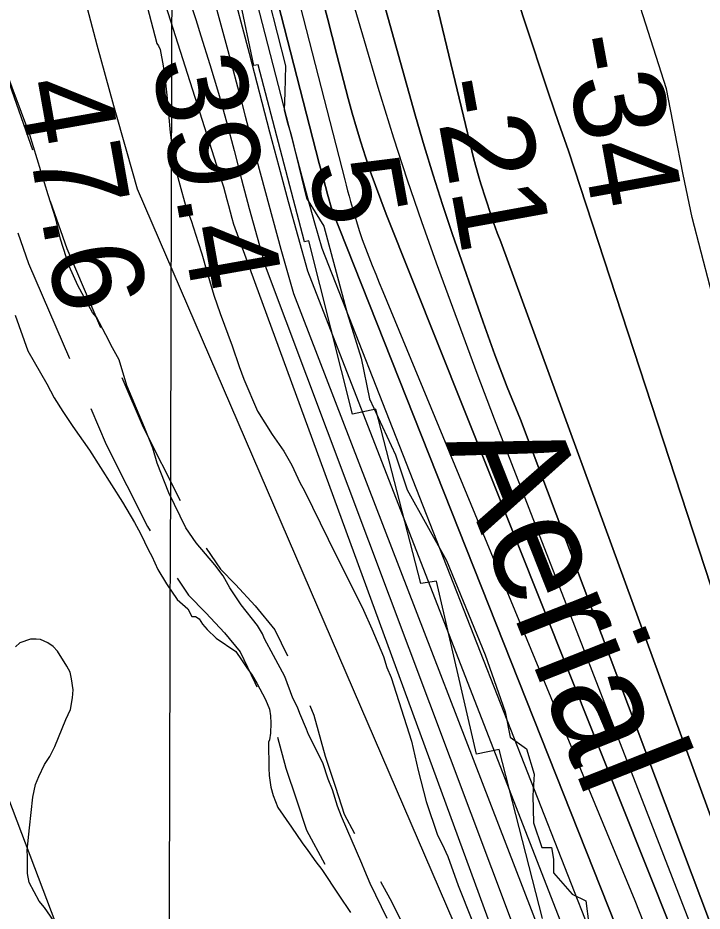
# Model space of a CAD drawing. Extents: x 3161665 to 3199565, y 885729 to 911164.
# Drawn here: x 3176224 to 3176727, y 893695 to 894352 of the extents above; entities that cross this region are included whole.
import ezdxf

# ---------------------------------------------------------------- set-up
doc = ezdxf.new("R2010")
doc.units = 0
for name, color, linetype in [('V-GRID-MAJR', 7, 'Continuous'), ('V-RIVR-EDGE', 7, 'Continuous'), ('V-RIVR-IDEN', 7, 'Continuous'), ('V-RIVR-RANG', 7, 'Continuous'), ('V-ROAD-CNTR', 7, 'Continuous'), ('V-RRAP-RVMT', 7, 'Continuous'), ('V-SITE-VEGE', 7, 'Continuous'), ('V-TOPO-DPTH', 7, 'Continuous'), ('V-TOPO-MAJR', 7, 'Continuous'), ('V-TOPO-MINR', 7, 'Continuous'), ('V-TOPO-WATR', 7, 'Continuous')]:
    doc.layers.add(name, color=color, linetype=linetype)

msp = doc.modelspace()

# ---------------------------------------------------------------- linework, layer by layer
at = {"layer": 'V-GRID-MAJR'}
msp.add_spline([(3176327.96, 891166.6), (3176345.58, 897226.3), (3176363.22, 903289.08), (3176380.86, 909351.9), (3176380.87, 909354.94)], degree=3, dxfattribs=at)
at = {"layer": 'V-RIVR-EDGE'}
for points in [[(3176294.76, 894759.71), (3176301.86, 894737.76), (3176313.25, 894714.84), (3176322.26, 894694.79), (3176326.51, 894678.57), (3176326.49, 894668.07), (3176330.26, 894651.37), (3176340.18, 894610.82), (3176343.47, 894594.12), (3176349.58, 894555.47), (3176354.81, 894552.12), (3176358.57, 894529.7), (3176365.2, 894509.66), (3176375.62, 894479.59), (3176392.64, 894422.8), (3176408.24, 894365.06), (3176420.52, 894316.86)], [(3176420.52, 894316.86), (3176419.99, 894297.31), (3176419.48, 894284.44), (3176421.85, 894275.85), (3176424.68, 894266.3), (3176436.01, 894219.54), (3176448.84, 894199), (3176465.85, 894135.06), (3176476.26, 894102.13), (3176482.38, 894072.07), (3176501.36, 894031.01), (3176509.88, 894005.24), (3176538.84, 893953.19), (3176567.28, 893883.97), (3176581.96, 893841.97), (3176585.73, 893823.36), (3176597.63, 893814.75), (3176603.3, 893796.14), (3176602.31, 893780.4), (3176602.74, 893760.37), (3176608.89, 893742.24), (3176616.05, 893742.22), (3176617.46, 893733.63), (3176617.43, 893723.62), (3176631.22, 893707.85), (3176641.22, 893703.05), (3176643.57, 893685.88)]]:
    msp.add_lwpolyline(points, dxfattribs=at)
at = {"layer": 'V-ROAD-CNTR'}
for points in [[(3176198.7, 894348.48), (3176199.62, 894345.85), (3176208.86, 894325.5), (3176216.14, 894308.46), (3176234.6, 894255.23)], [(3176247.7, 894217.44), (3176259.8, 894182.54), (3176284.62, 894124.57)], [(3176223.98, 894194.27), (3176231.81, 894171.71), (3176261.76, 894101.73)], [(3176300.36, 894087.79), (3176315.98, 894051.3), (3176343.09, 893997.44)], [(3176277.5, 894064.96), (3176288.76, 894038.64), (3176319.15, 893978.28), (3176320.99, 893974.96)], [(3176362.27, 893962.34), (3176362.32, 893962.24), (3176372.75, 893946.78), (3176383.73, 893935.48), (3176398.35, 893919.8), (3176412.62, 893902.36), (3176422.04, 893883.02)], [(3176340.93, 893940.31), (3176349.38, 893927.78), (3176362, 893914.8), (3176375.74, 893900.06), (3176387.18, 893886.08), (3176398.13, 893863.6), (3176399.56, 893860.34)], [(3176438.34, 893846.49), (3176441.42, 893839.42), (3176449.61, 893809.32), (3176457.25, 893786.5), (3176463.59, 893766.81), (3176471.38, 893752.45)], [(3176414.7, 893823.37), (3176420.89, 893800.61), (3176428.74, 893777.13), (3176435.89, 893754.95), (3176449.41, 893730.04)], [(3176490.46, 893717.29), (3176497.28, 893704.73), (3176536, 893628.32)]]:
    msp.add_lwpolyline(points, dxfattribs=at)
at = {"layer": 'V-RRAP-RVMT'}
for p, q in [((3176397.39, 894317.14), (3176370.51, 894442.62)), ((3176400.51, 894317.72), (3176397.39, 894317.14)), ((3176434.47, 894187.53), (3176400.51, 894317.72)), ((3176437.79, 894188.4), (3176434.47, 894187.53)), ((3176469.75, 894060.76), (3176437.79, 894188.4)), ((3176486.88, 894064.41), (3176469.75, 894060.76)), ((3176520.03, 893936.3), (3176486.88, 894064.41)), ((3176531.53, 893938), (3176520.03, 893936.3)), ((3176560.82, 893810.8), (3176531.53, 893938)), ((3176577.55, 893814.21), (3176560.82, 893810.8)), ((3176609.54, 893690.09), (3176577.55, 893814.21))]:
    msp.add_line(p, q, dxfattribs=at)
at = {"layer": 'V-SITE-VEGE'}
for p, q in [((3176221.9, 894133.61), (3176231.13, 894107.36)), ((3176231.13, 894107.36), (3176245.24, 894083.12)), ((3176245.24, 894083.12), (3176250.63, 894072.96)), ((3176250.63, 894072.96), (3176256.93, 894062.84)), ((3176256.93, 894062.84), (3176264.16, 894051.86)), ((3176264.16, 894051.86), (3176276.64, 894034.33)), ((3176276.64, 894034.33), (3176300.82, 893996.07)), ((3176300.82, 893996.07), (3176309.57, 893981.09)), ((3176309.57, 893981.09), (3176313.97, 893973.15)), ((3176313.97, 893973.15), (3176319.91, 893960.76)), ((3176319.91, 893960.76), (3176322.35, 893956.34)), ((3176322.35, 893956.34), (3176326.82, 893946.6)), ((3176326.82, 893946.6), (3176333.13, 893936.03)), ((3176333.13, 893936.03), (3176340.84, 893924.62)), ((3176340.84, 893924.62), (3176348.8, 893917.73)), ((3176348.8, 893917.73), (3176351.75, 893911.98)), ((3176351.75, 893911.98), (3176354.45, 893912.1)), ((3176354.45, 893912.1), (3176357.23, 893910.41)), ((3176357.23, 893910.41), (3176359.66, 893906.45)), ((3176359.66, 893906.45), (3176362.98, 893902.52)), ((3176362.98, 893902.52), (3176369.58, 893896.03)), ((3176233.27, 893895.27), (3176225.25, 893892.67)), ((3176237.33, 893895.44), (3176233.27, 893895.27)), ((3176240.5, 893895.12), (3176237.33, 893895.44)), ((3176246.02, 893892.64), (3176240.5, 893895.12)), ((3176369.58, 893896.03), (3176383.98, 893886.25)), ((3176225.25, 893892.67), (3176222.21, 893889.84)), ((3176249.74, 893890.09), (3176246.02, 893892.64)), ((3176253.05, 893886.62), (3176249.74, 893890.09)), ((3176259.83, 893875.62), (3176253.05, 893886.62)), ((3176383.98, 893886.25), (3176388.3, 893880.11)), ((3176262.27, 893871.21), (3176259.83, 893875.62)), ((3176388.3, 893880.11), (3176392.64, 893873.52)), ((3176263.38, 893866.29), (3176262.27, 893871.21)), ((3176392.64, 893873.52), (3176395.52, 893869.58)), ((3176395.52, 893869.58), (3176399.41, 893862.97)), ((3176264.62, 893858.21), (3176263.38, 893866.29)), ((3176399.41, 893862.97), (3176405.78, 893851.05)), ((3176263.97, 893852.32), (3176264.62, 893858.21)), ((3176262.53, 893843.68), (3176263.97, 893852.32)), ((3176405.78, 893851.05), (3176408.78, 893843.95)), ((3176259.22, 893836.32), (3176262.53, 893843.68)), ((3176408.78, 893843.95), (3176409.44, 893839.01)), ((3176251.02, 893816.56), (3176259.22, 893836.32)), ((3176409.44, 893839.01), (3176409.67, 893833.61)), ((3176409.67, 893833.61), (3176409.52, 893826.38)), ((3176409.52, 893826.38), (3176408.83, 893821.38)), ((3176247.27, 893809.18), (3176251.02, 893816.56)), ((3176408.83, 893821.38), (3176408, 893819.54)), ((3176408, 893819.54), (3176408.35, 893800.6)), ((3176243.46, 893803.15), (3176247.27, 893809.18)), ((3176239.32, 893794.4), (3176243.46, 893803.15)), ((3176408.35, 893800.6), (3176408.58, 893795.19)), ((3176236.86, 893788.43), (3176239.32, 893794.4)), ((3176408.58, 893795.19), (3176409.83, 893786.66)), ((3176234.98, 893779.32), (3176236.86, 893788.43)), ((3176409.83, 893786.66), (3176411.45, 893780.41)), ((3176232.32, 893756.63), (3176234.98, 893779.32)), ((3176411.45, 893780.41), (3176414.99, 893771.53)), ((3176414.99, 893771.53), (3176425.07, 893757.06)), ((3176230.75, 893740.32), (3176232.32, 893756.63)), ((3176425.07, 893757.06), (3176432.78, 893745.64)), ((3176432.78, 893745.64), (3176437.08, 893739.96)), ((3176230.96, 893735.36), (3176230.75, 893740.32)), ((3176437.08, 893739.96), (3176442.85, 893731.62)), ((3176231.02, 893723.17), (3176230.96, 893735.36)), ((3176442.85, 893731.62), (3176447.15, 893725.93)), ((3176232.21, 893716.45), (3176231.02, 893723.17)), ((3176447.15, 893725.93), (3176459.68, 893707.05)), ((3176239.55, 893702.77), (3176232.21, 893716.45)), ((3176459.68, 893707.05), (3176468.34, 893694.32)), ((3176243.37, 893697.96), (3176239.55, 893702.77)), ((3176254.9, 893681.29), (3176243.37, 893697.96))]:
    msp.add_line(p, q, dxfattribs=at)
for points in [[(3176318.9, 894360.69), (3176325.91, 894333.45), (3176327.34, 894331.71), (3176328.36, 894329.04), (3176330.67, 894316.95), (3176331.91, 894308.87), (3176333.38, 894295.39), (3176335.89, 894267.96), (3176338.68, 894244.6), (3176347.17, 894214.26), (3176351.25, 894203.15), (3176356.44, 894187.11), (3176359.05, 894178.64), (3176362.76, 894165.71), (3176368, 894148.32), (3176372.63, 894134.97), (3176381.31, 894110.96), (3176386.46, 894095.83), (3176390.01, 894086.5), (3176400.03, 894062.99), (3176410.68, 894045.83), (3176419.33, 894033.55), (3176425.17, 894023.41), (3176431.13, 894010.57), (3176434.55, 894004.4), (3176451.83, 893969.01), (3176477.95, 893916.83), (3176483.95, 893903.09), (3176492.48, 893882.68), (3176495.07, 893874.67), (3176498.1, 893867.12), (3176513.16, 893820.35), (3176518.12, 893798.89), (3176524.04, 893776.11), (3176532.31, 893751.18), (3176535.75, 893744.55), (3176539.74, 893735.69), (3176547.41, 893714.34)], [(3176495.16, 893690.03), (3176482.79, 893715.69), (3176478.79, 893725), (3176476.76, 893730.34), (3176461.76, 893764.92), (3176458.74, 893772.47), (3176455.07, 893784.5), (3176452.03, 893792.5), (3176447.91, 893804.52), (3176437.56, 893825.3), (3176436.03, 893829.3), (3176431.04, 893840.83), (3176429.49, 893845.28), (3176426.06, 893851.9), (3176419.97, 893867.9), (3176411.64, 893883.35), (3176405.25, 893895.72), (3176403.75, 893899.27), (3176399.88, 893905.43), (3176387.95, 893920.73), (3176379.76, 893933.02), (3176374.87, 893941.85), (3176368.66, 893950.16), (3176354.89, 893966.29), (3176347.2, 893977.25), (3176334.84, 894002.92), (3176326.25, 894024.68), (3176323.07, 894035.83), (3176317.02, 894050.92), (3176303.98, 894081.98), (3176298.23, 894100.7), (3176293.34, 894109.52), (3176288.42, 894119.24), (3176281.56, 894132.05), (3176278.7, 894135.54), (3176267.94, 894155.4), (3176261.47, 894169.58), (3176255.21, 894189.63), (3176251.88, 894204.39), (3176246.17, 894222.2), (3176232.58, 894266.33), (3176207.16, 894333.88)], [(3176547.41, 893714.34), (3176557.5, 893689.04)]]:
    msp.add_lwpolyline(points, dxfattribs=at)
at = {"layer": 'V-TOPO-DPTH'}
for points in [[(3176701.72, 893587.62), (3176454.57, 894211.21), (3176451.43, 894222.51), (3176448.39, 894233.82), (3176445.42, 894245.16), (3176396.2, 894436.23), (3176377.64, 894508.46), (3176359.12, 894580.69), (3176340.69, 894652.95), (3176322.3, 894725.22), (3176300.56, 894810.9)], [(3176701.72, 893587.62), (3176454.57, 894211.21), (3176451.43, 894222.51), (3176448.39, 894233.82), (3176445.42, 894245.16), (3176396.2, 894436.23), (3176377.64, 894508.46), (3176359.12, 894580.69), (3176340.69, 894652.95), (3176322.3, 894725.22), (3176300.56, 894810.9)], [(3176474.19, 894812.27), (3176539.01, 894548.12), (3176551.8, 894498.57), (3176565.37, 894449.24), (3176580.12, 894400.26), (3176595.65, 894351.5), (3176614.05, 894296.04), (3176621.17, 894275.25), (3176628.57, 894254.57), (3176855.03, 893561.59), (3176864.47, 893534.44), (3176874.25, 893507.41), (3176905.05, 893424.69), (3176928.25, 893364.03), (3176952.17, 893303.67), (3176977.16, 893243.75), (3177002.88, 893184.12), (3177037.17, 893106.53), (3177046.52, 893086.03), (3177056.18, 893065.69), (3177066.33, 893045.59), (3177076.79, 893025.64), (3177087.65, 893005.9)], [(3177087.65, 893005.9), (3177076.79, 893025.64), (3177066.33, 893045.59), (3177056.18, 893065.69), (3177046.52, 893086.03), (3177037.17, 893106.53), (3177002.88, 893184.12), (3176977.16, 893243.75), (3176952.17, 893303.67), (3176928.25, 893364.03), (3176905.05, 893424.69), (3176874.25, 893507.41), (3176864.47, 893534.44), (3176855.03, 893561.59), (3176628.57, 894254.57), (3176621.17, 894275.25), (3176614.05, 894296.04), (3176595.65, 894351.5), (3176580.12, 894400.26), (3176565.37, 894449.24), (3176551.8, 894498.57), (3176539.01, 894548.12), (3176474.19, 894812.27)], [(3176378.37, 894796.48), (3176432.92, 894586.18), (3176448.26, 894527.72), (3176463.81, 894469.33), (3176479.69, 894411.02), (3176495.78, 894352.77), (3176516.14, 894279.85), (3176522.42, 894258.17), (3176528.96, 894236.56), (3176535.91, 894215.08), (3176543.12, 894193.69), (3176565.75, 894128.57), (3176574.44, 894104.53), (3176583.53, 894080.64), (3176593.22, 894056.99), (3176785.41, 893546.84)], [(3176785.41, 893546.84), (3176593.22, 894056.99), (3176583.53, 894080.64), (3176574.44, 894104.53), (3176565.75, 894128.57), (3176543.12, 894193.69), (3176535.91, 894215.08), (3176528.96, 894236.56), (3176522.42, 894258.17), (3176516.14, 894279.85), (3176495.78, 894352.77), (3176479.69, 894411.02), (3176463.81, 894469.33), (3176448.26, 894527.72), (3176432.92, 894586.18), (3176378.37, 894796.48)], [(3176429.03, 894790.23), (3176441.16, 894739.42), (3176453.3, 894688.61), (3176465.46, 894637.81), (3176477.63, 894587.02), (3176557.4, 894254.39), (3176558.94, 894248.28), (3176560.57, 894242.2), (3176562.33, 894236.15), (3176564.18, 894230.13), (3176571.35, 894207.76), (3176573.68, 894200.96), (3176576.17, 894194.23), (3176578.93, 894187.59), (3176812.57, 893547.36)], [(3176812.57, 893547.36), (3176578.93, 894187.59), (3176576.17, 894194.23), (3176573.68, 894200.96), (3176571.35, 894207.76), (3176564.18, 894230.13), (3176562.33, 894236.15), (3176560.57, 894242.2), (3176558.94, 894248.28), (3176557.4, 894254.39), (3176477.63, 894587.02), (3176465.46, 894637.81), (3176453.3, 894688.61), (3176441.16, 894739.42), (3176429.03, 894790.23)], [(3176266.9, 894771.62), (3176333.82, 894543.75), (3176349.45, 894489.57), (3176364.72, 894435.3), (3176379.47, 894380.89), (3176393.87, 894326.38), (3176408.84, 894268.55), (3176415.58, 894242.9), (3176422.46, 894217.29), (3176429.52, 894191.74), (3176436.72, 894166.21), (3176659.83, 893591.97)], [(3176723.83, 893632.92), (3176494.51, 894207.93), (3176490.51, 894218.39), (3176486.62, 894228.89), (3176482.9, 894239.45), (3176479.31, 894250.06), (3176475.9, 894260.73), (3176472.63, 894271.44), (3176469.57, 894282.21), (3176466.65, 894293.02), (3176458.31, 894325.08), (3176451.32, 894351.95), (3176444.33, 894378.83), (3176437.34, 894405.7), (3176430.36, 894432.58), (3176370.31, 894663.81), (3176361.21, 894699.06), (3176352.17, 894734.32), (3176343.24, 894769.61)], [(3176343.24, 894769.61), (3176352.17, 894734.32), (3176361.21, 894699.06), (3176370.31, 894663.81), (3176430.36, 894432.58), (3176437.34, 894405.7), (3176444.33, 894378.83), (3176451.32, 894351.95), (3176458.31, 894325.08), (3176466.65, 894293.02), (3176469.57, 894282.21), (3176472.63, 894271.44), (3176475.9, 894260.73), (3176479.31, 894250.06), (3176482.9, 894239.45), (3176486.62, 894228.89), (3176490.51, 894218.39), (3176494.51, 894207.93), (3176723.83, 893632.92)]]:
    msp.add_lwpolyline(points, dxfattribs=at)
at = {"layer": 'V-TOPO-MAJR'}
for points in [[(3176197.14, 894785.58), (3176371.51, 894238.53), (3176372.03, 894236.97), (3176373.49, 894232.46), (3176374.88, 894227.92), (3176376.17, 894223.35), (3176377.39, 894218.76), (3176378.58, 894214.17), (3176379.8, 894209.58), (3176381.04, 894204.99), (3176382.31, 894200.42), (3176605.45, 893591.02)], [(3177266.38, 892869.65), (3176888.97, 893555.49), (3176884.77, 893568.13), (3176719.38, 894205.41), (3176712.92, 894236.95), (3176706.65, 894268.53), (3176700.65, 894300.16), (3176561.53, 894735.82), (3176550.46, 894770.02)]]:
    msp.add_lwpolyline(points, dxfattribs=at)
at = {"layer": 'V-TOPO-MINR'}
for points in [[(3176212.29, 894808.98), (3176230.66, 894733.5), (3176345.79, 894377.75), (3176354.6, 894350.93), (3176358.44, 894338.97), (3176364.98, 894318.01), (3176371.26, 894296.98), (3176377.16, 894275.84), (3176382.8, 894254.62), (3176388.34, 894233.37), (3176393.98, 894212.15), (3176399.77, 894190.97), (3176405.67, 894169.82), (3176602.22, 893646.03)], [(3177087.65, 893005.9), (3177076.79, 893025.64), (3177066.33, 893045.59), (3177056.18, 893065.69), (3177046.52, 893086.03), (3177037.17, 893106.53), (3177002.88, 893184.12), (3176977.16, 893243.75), (3176952.17, 893303.67), (3176928.25, 893364.03), (3176905.05, 893424.69), (3176874.25, 893507.41), (3176864.47, 893534.44), (3176855.03, 893561.59), (3176628.57, 894254.57), (3176621.17, 894275.25), (3176614.05, 894296.04), (3176595.65, 894351.5), (3176580.12, 894400.26), (3176565.37, 894449.24), (3176551.8, 894498.57), (3176539.01, 894548.12), (3176474.19, 894812.27)], [(3176378.37, 894796.48), (3176432.92, 894586.18), (3176448.26, 894527.72), (3176463.81, 894469.33), (3176479.69, 894411.02), (3176495.78, 894352.77), (3176516.14, 894279.85), (3176522.42, 894258.17), (3176528.96, 894236.56), (3176535.91, 894215.08), (3176543.12, 894193.69), (3176565.75, 894128.57), (3176574.44, 894104.53), (3176583.53, 894080.64), (3176593.22, 894056.99), (3176785.41, 893546.84)], [(3176237.21, 894792.25), (3176245.63, 894759.57), (3176254.61, 894727.06), (3176264.46, 894694.8), (3176274.88, 894662.7), (3176277.82, 894654.02), (3176289.99, 894617.66), (3176301.95, 894581.23), (3176313.6, 894544.7), (3176325.05, 894508.11), (3176345.67, 894441.23), (3176356.94, 894403.72), (3176367.86, 894366.12), (3176378.26, 894328.36), (3176388.29, 894290.5), (3176390.99, 894280.05), (3176399.54, 894247.37), (3176408.25, 894214.74), (3176417.21, 894182.17), (3176426.33, 894149.65), (3176649.02, 893572.21)], [(3176289.07, 894792.73), (3176325.52, 894650.59), (3176343.96, 894578.78), (3176362.42, 894506.97), (3176380.94, 894435.17), (3176399.48, 894363.38), (3176427.01, 894256.93), (3176431.88, 894238.39), (3176436.85, 894219.88), (3176441.98, 894201.42), (3176447.2, 894182.97), (3176692.44, 893557.31)], [(3176812.57, 893547.36), (3176578.93, 894187.59), (3176576.17, 894194.23), (3176573.68, 894200.96), (3176571.35, 894207.76), (3176564.18, 894230.13), (3176562.33, 894236.15), (3176560.57, 894242.2), (3176558.94, 894248.28), (3176557.4, 894254.39), (3176477.63, 894587.02), (3176465.46, 894637.81), (3176453.3, 894688.61), (3176441.16, 894739.42), (3176429.03, 894790.23)], [(3176356.95, 894781.94), (3176367.71, 894741.69), (3176377.38, 894705.54), (3176387.07, 894669.38), (3176396.79, 894633.24), (3176406.52, 894597.1), (3176449.18, 894438.88), (3176458.64, 894404.4), (3176468.3, 894369.97), (3176478.27, 894335.64), (3176488.43, 894301.36), (3176490.4, 894294.83), (3176500.01, 894263.95), (3176509.97, 894233.19), (3176520.48, 894202.61), (3176531.35, 894172.14), (3176561.11, 894091.01), (3176573.81, 894057.29), (3176757.34, 893584.36)], [(3176266.9, 894771.62), (3176333.82, 894543.75), (3176349.45, 894489.57), (3176364.72, 894435.3), (3176379.47, 894380.89), (3176393.87, 894326.38), (3176408.84, 894268.55), (3176415.58, 894242.9), (3176422.46, 894217.29), (3176429.52, 894191.74), (3176436.72, 894166.21), (3176659.83, 893591.97)], [(3176343.24, 894769.61), (3176352.17, 894734.32), (3176361.21, 894699.06), (3176370.31, 894663.81), (3176430.36, 894432.58), (3176437.34, 894405.7), (3176444.33, 894378.83), (3176451.32, 894351.95), (3176458.31, 894325.08), (3176466.65, 894293.02), (3176469.57, 894282.21), (3176472.63, 894271.44), (3176475.9, 894260.73), (3176479.31, 894250.06), (3176482.9, 894239.45), (3176486.62, 894228.89), (3176490.51, 894218.39), (3176494.51, 894207.93), (3176723.83, 893632.92)], [(3176180.84, 894761.9), (3176248.36, 894467.34), (3176259.04, 894422.27), (3176270.15, 894377.31), (3176281.93, 894332.52), (3176294.14, 894287.84), (3176303.62, 894254.1), (3176311.55, 894226.41), (3176612.77, 893527.63), (3176613.34, 893526.85), (3176614.88, 893524.42), (3176616.12, 893521.83), (3176616.47, 893520.93), (3176617.94, 893516.84), (3176618.35, 893515.67), (3176619.56, 893512.15), (3176762.91, 893082.18), (3176779.18, 893033.14), (3176795.37, 892984.08)], [(3176328.37, 894764.38), (3176342.01, 894710.25), (3176355.7, 894656.13), (3176369.48, 894602.04), (3176383.31, 894547.96), (3176464.05, 894233.22), (3176465.1, 894229.18), (3176466.19, 894225.16), (3176467.31, 894221.14), (3176468.45, 894217.13), (3176472.74, 894202.41), (3176474.75, 894195.85), (3176476.9, 894189.34), (3176479.24, 894182.89), (3176481.71, 894176.5), (3176484.3, 894170.13), (3176486.89, 894163.78), (3176489.51, 894157.43), (3176492.14, 894151.09), (3176677.17, 893703.29), (3176683.67, 893687.16)], [(3176568.91, 892934.65), (3176340.59, 893441.26), (3176336.7, 893450.17), (3176332.96, 893459.12), (3176329.43, 893468.17), (3176326.05, 893477.27), (3176322.85, 893486.45), (3176319.75, 893495.65), (3176316.81, 893504.91), (3176313.97, 893514.2), (3176311.3, 893523.21), (3176307.05, 893536.99), (3176302.6, 893550.69), (3176297.85, 893564.29), (3176292.89, 893577.82), (3176188.35, 893853.51), (3176169.56, 893903.6), (3176151, 893953.77), (3176132.79, 894004.07), (3176114.82, 894054.46), (3176079.71, 894153.96), (3176079.49, 894154.66), (3176078.96, 894156.82), (3176062.34, 894249.64)]]:
    msp.add_lwpolyline(points, dxfattribs=at)
at = {"layer": 'V-TOPO-WATR'}
msp.add_lwpolyline([(3176300.56, 894810.9), (3176322.3, 894725.22), (3176340.69, 894652.95), (3176359.12, 894580.69), (3176377.64, 894508.46), (3176396.2, 894436.23), (3176445.42, 894245.16), (3176448.39, 894233.82), (3176451.43, 894222.51), (3176454.57, 894211.21), (3176701.72, 893587.62)], dxfattribs=at)

# ---------------------------------------------------------------- texts
at = {"layer": 'V-RIVR-IDEN'}
msp.add_text('Aerial', height=83, rotation=291.59001, dxfattribs=at).set_placement((3176537.57, 894040.29))
at = {"layer": 'V-RIVR-RANG'}
for s, rotation, p in [('-34', 280.35806, (3176623.49, 894336.53)), ('39.4', 280.07833, (3176322.16, 894319.88)), ('47.6', 280.07833, (3176223.42, 894303.94)), ('-21', 280.35806, (3176527.64, 894304.77)), ('5', 280.35806, (3176436.96, 894244.73))]:
    msp.add_text(s, height=67, rotation=rotation, dxfattribs=at).set_placement(p)

doc.saveas('drawing.dxf')
